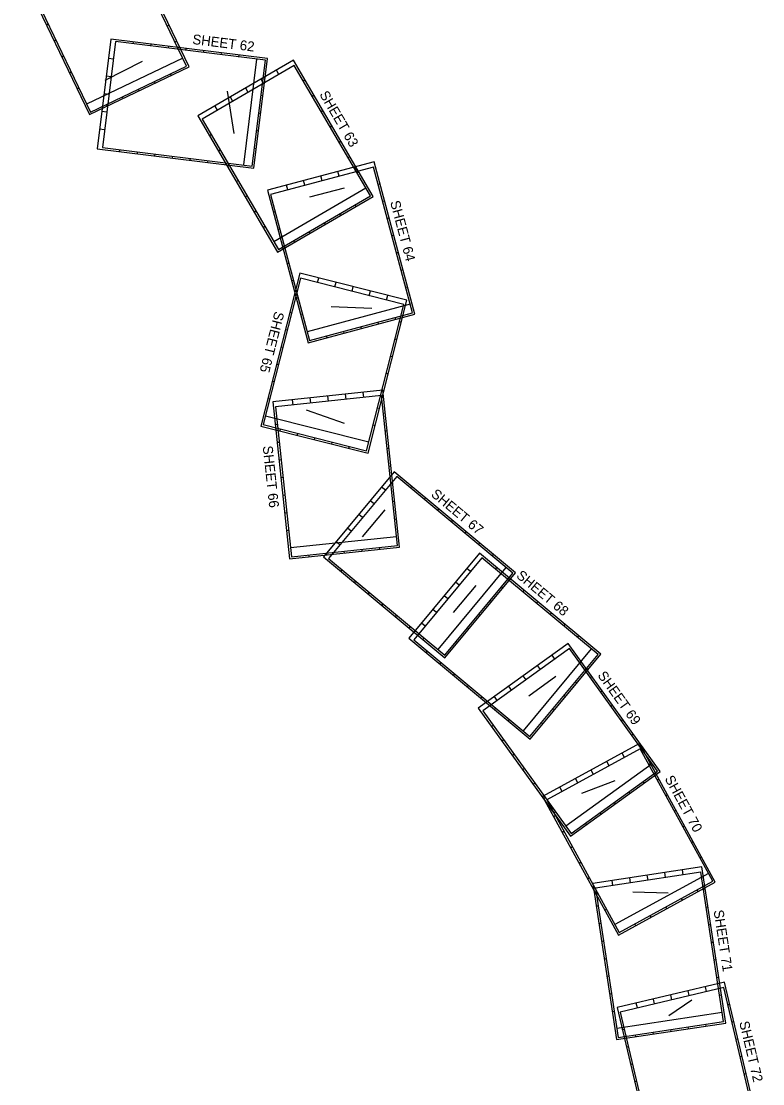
# Model space of a CAD drawing. Extents: x 518852 to 589310, y 1937169 to 2155394.
# Drawn here: x 560866 to 579649, y 1966083 to 1993000 of the extents above; entities that cross this region are included whole.
import ezdxf

# ---------------------------------------------------------------- set-up
doc = ezdxf.new("R2010")
doc.units = 0
doc.layers.add('Level 1', color=7, linetype='Continuous')
doc.layers.add('Level 58', color=7, linetype='Continuous')

msp = doc.modelspace()

# ---------------------------------------------------------------- linework, layer by layer
at = {"layer": 'Level 1'}
for p, q in [((561503, 1992911), (561548, 1992933)), ((564566, 1992881), (564611, 1992902)), ((561697, 1992505), (561742, 1992527)), ((563701, 1992429), (563708, 1992478)), ((564148, 1992373), (564154, 1992422)), ((564594, 1992317), (564601, 1992367)), ((564760, 1992475), (564806, 1992496)), ((561891, 1992099), (561936, 1992121)), ((565041, 1992261), (565047, 1992311)), ((565488, 1992206), (565494, 1992255)), ((565934, 1992150), (565940, 1992200)), ((566381, 1992094), (566387, 1992144)), ((564955, 1992069), (562519, 1990903)), ((563199, 1992038), (563075, 1992053)), ((566827, 1992038), (566493, 1989359)), ((562086, 1991693), (562131, 1991715)), ((563143, 1991591), (563019, 1991607)), ((564668, 1991627), (564646, 1991672)), ((567044, 1991558), (566995, 1991564)), ((567392, 1991652), (567329, 1991760)), ((562280, 1991287), (562325, 1991309)), ((564262, 1991432), (564240, 1991477)), ((566615, 1991198), (566552, 1991306)), ((567004, 1991425), (566941, 1991533)), ((568008, 1991491), (568051, 1991516)), ((563088, 1991145), (562964, 1991160)), ((563450, 1991044), (563428, 1991089)), ((563856, 1991238), (563834, 1991283)), ((566227, 1990971), (566164, 1991079)), ((566989, 1991111), (566939, 1991117)), ((568235, 1991102), (568278, 1991128)), ((563044, 1990849), (563022, 1990895)), ((565838, 1990744), (565775, 1990852)), ((563032, 1990698), (562908, 1990714)), ((566933, 1990665), (566883, 1990671)), ((568462, 1990714), (568505, 1990739)), ((562976, 1990252), (562852, 1990267)), ((566877, 1990218), (566827, 1990224)), ((568689, 1990325), (568732, 1990350)), ((565633, 1990104), (565677, 1990129)), ((568916, 1989937), (568959, 1989962)), ((563361, 1989700), (563367, 1989749)), ((563807, 1989644), (563814, 1989694)), ((565860, 1989715), (565904, 1989740)), ((566821, 1989772), (566772, 1989778)), ((564254, 1989588), (564260, 1989638)), ((564700, 1989533), (564707, 1989582)), ((565147, 1989477), (565153, 1989526)), ((565593, 1989421), (565600, 1989471)), ((566040, 1989365), (566046, 1989415)), ((569143, 1989548), (569186, 1989573)), ((566087, 1989327), (566131, 1989352)), ((568921, 1989075), (568889, 1989196)), ((569356, 1989191), (569324, 1989312)), ((569370, 1989160), (569413, 1989185)), ((566314, 1988938), (566358, 1988963)), ((568051, 1988844), (568019, 1988964)), ((568486, 1988960), (568454, 1989080)), ((569907, 1988872), (569955, 1988885)), ((569597, 1988771), (567266, 1987409)), ((567617, 1988728), (567584, 1988849)), ((566541, 1988549), (566585, 1988575)), ((569347, 1988307), (569322, 1988350)), ((570023, 1988438), (570071, 1988451)), ((566768, 1988161), (566812, 1988186)), ((567249, 1988164), (567298, 1988177)), ((568958, 1988080), (568933, 1988123)), ((566995, 1987772), (567039, 1987798)), ((568570, 1987853), (568545, 1987896)), ((570138, 1988003), (570187, 1988016)), ((567365, 1987729), (567414, 1987742)), ((568181, 1987626), (568156, 1987669)), ((570254, 1987568), (570303, 1987581)), ((567481, 1987295), (567529, 1987307)), ((567793, 1987399), (567768, 1987442)), ((570370, 1987133), (570419, 1987146)), ((567597, 1986860), (567645, 1986873)), ((568373, 1986378), (568403, 1986499)), ((570486, 1986698), (570534, 1986711)), ((567713, 1986425), (567761, 1986438)), ((568809, 1986268), (568840, 1986389)), ((569245, 1986157), (569276, 1986279)), ((570602, 1986264), (570650, 1986276)), ((567778, 1986065), (567826, 1986052)), ((567829, 1985990), (567877, 1986003)), ((569681, 1986047), (569712, 1986168)), ((570118, 1985937), (570148, 1986058)), ((570718, 1985829), (568109, 1985133)), ((567667, 1985628), (567716, 1985616)), ((567945, 1985555), (567993, 1985568)), ((569919, 1985331), (569906, 1985380)), ((570354, 1985447), (570341, 1985495)), ((570443, 1985390), (570492, 1985378)), ((567557, 1985192), (567605, 1985180)), ((569049, 1985099), (569037, 1985148)), ((569484, 1985215), (569471, 1985264)), ((568615, 1984984), (568602, 1985032)), ((570333, 1984954), (570382, 1984941)), ((567446, 1984756), (567495, 1984744)), ((567336, 1984320), (567384, 1984307)), ((570223, 1984518), (570271, 1984505)), ((570112, 1984081), (570161, 1984069)), ((567226, 1983883), (567274, 1983871)), ((568646, 1983379), (568633, 1983503)), ((569093, 1983427), (569080, 1983551)), ((569541, 1983474), (569528, 1983599)), ((570002, 1983645), (570050, 1983633)), ((567115, 1983447), (567164, 1983435)), ((567751, 1983284), (567738, 1983408)), ((568198, 1983332), (568185, 1983456)), ((569671, 1982336), (567053, 1982999)), ((569891, 1983209), (569940, 1983197)), ((570036, 1983074), (570086, 1983080)), ((567301, 1982784), (567351, 1982789)), ((569781, 1982773), (569830, 1982760)), ((567422, 1982622), (567434, 1982670)), ((567858, 1982511), (567870, 1982560)), ((568294, 1982401), (568307, 1982449)), ((570083, 1982627), (570133, 1982632)), ((567349, 1982336), (567399, 1982341)), ((568731, 1982290), (568743, 1982339)), ((569167, 1982180), (569179, 1982229)), ((570131, 1982180), (570181, 1982185)), ((567396, 1981889), (567446, 1981894)), ((570179, 1981732), (570228, 1981737)), ((567444, 1981441), (567494, 1981446)), ((570090, 1981119), (569994, 1981199)), ((570226, 1981285), (570276, 1981290)), ((570724, 1981177), (570756, 1981216)), ((567492, 1980994), (567541, 1980999)), ((569802, 1980773), (569706, 1980853)), ((570274, 1980837), (570324, 1980842)), ((571070, 1980890), (571102, 1980928)), ((567539, 1980546), (567589, 1980552)), ((571416, 1980602), (571448, 1980640)), ((569514, 1980427), (569418, 1980507)), ((570321, 1980390), (570371, 1980395)), ((571762, 1980314), (571793, 1980352)), ((567587, 1980099), (567637, 1980104)), ((569227, 1980081), (569130, 1980161)), ((572107, 1980026), (572139, 1980065)), ((570369, 1979942), (567684, 1979657)), ((568939, 1979735), (568843, 1979815)), ((572453, 1979738), (572485, 1979777)), ((568161, 1979431), (568155, 1979480)), ((568608, 1979478), (568603, 1979528)), ((569056, 1979526), (569050, 1979576)), ((569503, 1979573), (569498, 1979623)), ((569951, 1979621), (569945, 1979671)), ((572799, 1979451), (572831, 1979489)), ((568965, 1979063), (568997, 1979102)), ((573145, 1979163), (571419, 1977087)), ((572250, 1979057), (572154, 1979137)), ((572883, 1979115), (572915, 1979154)), ((569311, 1978775), (569343, 1978814)), ((571962, 1978711), (571866, 1978791)), ((573069, 1978641), (573030, 1978673)), ((573229, 1978827), (573261, 1978866)), ((569657, 1978488), (569689, 1978526)), ((571674, 1978365), (571578, 1978445)), ((573575, 1978539), (573607, 1978578)), ((570003, 1978200), (570035, 1978238)), ((572781, 1978295), (572743, 1978327)), ((573921, 1978252), (573953, 1978290)), ((570349, 1977912), (570381, 1977951)), ((571386, 1978019), (571290, 1978099)), ((572493, 1977949), (572455, 1977981)), ((574267, 1977964), (574299, 1978002)), ((570695, 1977624), (570727, 1977663)), ((571099, 1977673), (571002, 1977753)), ((572206, 1977603), (572167, 1977635)), ((574613, 1977676), (574645, 1977715)), ((571041, 1977336), (571073, 1977375)), ((574959, 1977388), (574991, 1977427)), ((571125, 1977001), (571157, 1977039)), ((571918, 1977257), (571879, 1977289)), ((575305, 1977101), (573578, 1975025)), ((574384, 1976843), (574311, 1976945)), ((575012, 1976741), (575053, 1976770)), ((571471, 1976713), (571503, 1976752)), ((574019, 1976580), (573946, 1976682)), ((575229, 1976579), (575190, 1976611)), ((571817, 1976425), (571849, 1976464)), ((573654, 1976318), (573581, 1976419)), ((574941, 1976233), (574902, 1976265)), ((575275, 1976375), (575316, 1976405)), ((572163, 1976138), (572194, 1976176)), ((573288, 1976055), (573215, 1976156)), ((575538, 1976010), (575579, 1976039)), ((572508, 1975850), (572540, 1975888)), ((572923, 1975792), (572850, 1975893)), ((574653, 1975887), (574615, 1975919)), ((572854, 1975562), (572886, 1975600)), ((574365, 1975541), (574327, 1975573)), ((575801, 1975645), (575841, 1975674)), ((572780, 1975135), (572821, 1975164)), ((573200, 1975274), (573232, 1975313)), ((574077, 1975195), (574039, 1975227)), ((576064, 1975280), (576104, 1975309)), ((576327, 1974914), (576367, 1974944)), ((573043, 1974769), (573084, 1974798)), ((573306, 1974404), (573346, 1974433)), ((576150, 1974352), (576090, 1974461)), ((576589, 1974549), (576630, 1974578)), ((573569, 1974039), (573609, 1974068)), ((576852, 1974184), (574661, 1972607)), ((575755, 1974136), (575696, 1974245)), ((576761, 1974173), (576805, 1974197)), ((574966, 1973704), (574906, 1973814)), ((575361, 1973920), (575301, 1974030)), ((576977, 1973778), (577021, 1973802)), ((573831, 1973673), (573872, 1973703)), ((574571, 1973488), (574511, 1973598)), ((576647, 1973698), (576618, 1973738)), ((574094, 1973308), (574135, 1973337)), ((576282, 1973435), (576253, 1973476)), ((577193, 1973383), (577237, 1973407)), ((575917, 1973172), (575888, 1973213)), ((577409, 1972988), (577453, 1973012)), ((574348, 1972853), (574392, 1972877)), ((574357, 1972943), (574398, 1972972)), ((575552, 1972909), (575522, 1972950)), ((574564, 1972458), (574608, 1972482)), ((575186, 1972646), (575157, 1972687)), ((577625, 1972594), (577669, 1972618)), ((577841, 1972199), (577885, 1972223)), ((574780, 1972064), (574824, 1972088)), ((574996, 1971669), (575040, 1971693)), ((578057, 1971804), (578101, 1971828)), ((578273, 1971409), (575904, 1970114)), ((577189, 1971310), (577170, 1971433)), ((577634, 1971377), (577615, 1971501)), ((575212, 1971274), (575256, 1971298)), ((575854, 1971107), (575835, 1971230)), ((576299, 1971174), (576280, 1971298)), ((576744, 1971242), (576725, 1971366)), ((575428, 1970879), (575472, 1970903)), ((578010, 1970952), (577986, 1970996)), ((578146, 1971000), (578196, 1971008)), ((575427, 1970587), (575477, 1970594)), ((577615, 1970736), (577591, 1970780)), ((575644, 1970484), (575688, 1970508)), ((576825, 1970304), (576801, 1970348)), ((577220, 1970520), (577196, 1970564)), ((578214, 1970555), (578263, 1970563)), ((575495, 1970142), (575544, 1970149)), ((576431, 1970088), (576407, 1970132)), ((578281, 1970110), (578331, 1970118)), ((575563, 1969697), (575612, 1969704)), ((578349, 1969666), (578399, 1969673)), ((575630, 1969252), (575680, 1969259)), ((578417, 1969221), (578466, 1969228)), ((575698, 1968807), (575747, 1968815)), ((578484, 1968776), (578534, 1968783)), ((577787, 1968316), (577758, 1968437)), ((578225, 1968419), (578196, 1968541)), ((575766, 1968362), (575815, 1968370)), ((576911, 1968108), (576882, 1968230)), ((577349, 1968212), (577320, 1968333)), ((578552, 1968331), (578602, 1968338)), ((575833, 1967917), (575883, 1967925)), ((578620, 1967886), (575951, 1967480)), ((576473, 1968004), (576444, 1968126)), ((578766, 1968085), (578815, 1968097)), ((578870, 1967647), (578919, 1967659)), ((576090, 1967451), (576139, 1967463)), ((576882, 1967343), (576874, 1967393)), ((577327, 1967411), (577319, 1967461)), ((577771, 1967479), (577764, 1967528)), ((578216, 1967546), (578209, 1967596)), ((576437, 1967276), (576429, 1967325)), ((578974, 1967209), (579022, 1967221)), ((576194, 1967013), (576243, 1967025)), ((576298, 1966575), (576347, 1966587)), ((579078, 1966771), (579126, 1966783)), ((579181, 1966334), (579230, 1966345)), ((576402, 1966138), (576450, 1966149))]:
    msp.add_line(p, q, dxfattribs=at)
for points in [[(560866, 1994241), (562593, 1990634), (565119, 1991842), (563392, 1995450)], [(560965, 1994150), (562617, 1990700), (565052, 1991866), (563400, 1995316)], [(562790, 1989771), (566759, 1989276), (567106, 1992054), (563137, 1992549)], [(562920, 1989805), (566716, 1989331), (567050, 1992011), (563255, 1992484)], [(565343, 1990600), (567361, 1987146), (569779, 1988559), (567761, 1992013)], [(565450, 1990517), (567379, 1987215), (569710, 1988577), (567781, 1991879)], [(567101, 1988720), (568131, 1984855), (570837, 1985576), (569807, 1989441)], [(567182, 1988612), (568167, 1984916), (570776, 1985611), (569791, 1989307)], [(567919, 1986622), (566937, 1982744), (569652, 1982057), (570633, 1985935)], [(567936, 1986489), (566998, 1982781), (569615, 1982118), (570554, 1985826)], [(567240, 1983355), (567664, 1979378), (570448, 1979674), (570025, 1983652)], [(567303, 1983236), (567708, 1979433), (570393, 1979718), (569988, 1983522)], [(568523, 1979431), (571598, 1976873), (573389, 1979025), (570314, 1981584)], [(568651, 1979389), (571592, 1976943), (573318, 1979019), (570378, 1981465)], [(570683, 1977369), (573758, 1974811), (575548, 1976963), (572473, 1979521)], [(570811, 1977327), (573751, 1974881), (575478, 1976957), (572537, 1979403)], [(572444, 1975601), (574781, 1972354), (577053, 1973990), (574717, 1977237)], [(572558, 1975529), (574792, 1972424), (576984, 1974001), (574750, 1977106)], [(574072, 1973358), (575992, 1969848), (578448, 1971192), (576529, 1974701)], [(574176, 1973272), (576012, 1969916), (578381, 1971212), (576545, 1974568)], [(575341, 1971155), (575942, 1967201), (578711, 1967622), (578109, 1971576)], [(575409, 1971039), (575984, 1967258), (578654, 1967664), (578078, 1971445)], [(575958, 1968011), (576880, 1964118), (579604, 1964764), (578682, 1968656)], [(576035, 1967901), (576917, 1964179), (579544, 1964801), (578663, 1968523)]]:
    msp.add_lwpolyline(points, close=True, dxfattribs=at)
at = {"layer": 'Level 58'}
for p, q in [((562992, 1991511), (563941, 1991988)), ((566263, 1990154), (566092, 1991227)), ((568180, 1988548), (569052, 1988780)), ((568714, 1985777), (569749, 1985735)), ((568084, 1983155), (569047, 1982818)), ((570073, 1980620), (569504, 1979936)), ((572379, 1978702), (571810, 1978018)), ((573726, 1975914), (574409, 1976405)), ((575069, 1973446), (575909, 1973766)), ((576360, 1970947), (577250, 1970918)), ((577267, 1967814), (577850, 1968213))]:
    msp.add_line(p, q, dxfattribs=at)

# ---------------------------------------------------------------- texts
for s, rotation, p in [('SHEET 62', 352.8848, (565191, 1992426)), ('SHEET 63', 300.2946, (568411, 1991148)), ('SHEET 64', 284.9245, (570208, 1988422)), ('SHEET 65', 255.7981, (567290, 1985667)), ('SHEET 66', 276.0718, (566983, 1982234)), ('SHEET 67', 320.2434, (571228, 1980985)), ('SHEET 68', 320.2434, (573387, 1978924)), ('SHEET 69', 305.736, (575454, 1976427)), ('SHEET 70', 298.6764, (577158, 1973812)), ('SHEET 71', 278.65, (578404, 1970471)), ('SHEET 72', 283.3261, (579052, 1967640))]:
    msp.add_text(s, height=250, rotation=rotation, dxfattribs=at).set_placement(p)

doc.saveas('drawing.dxf')
